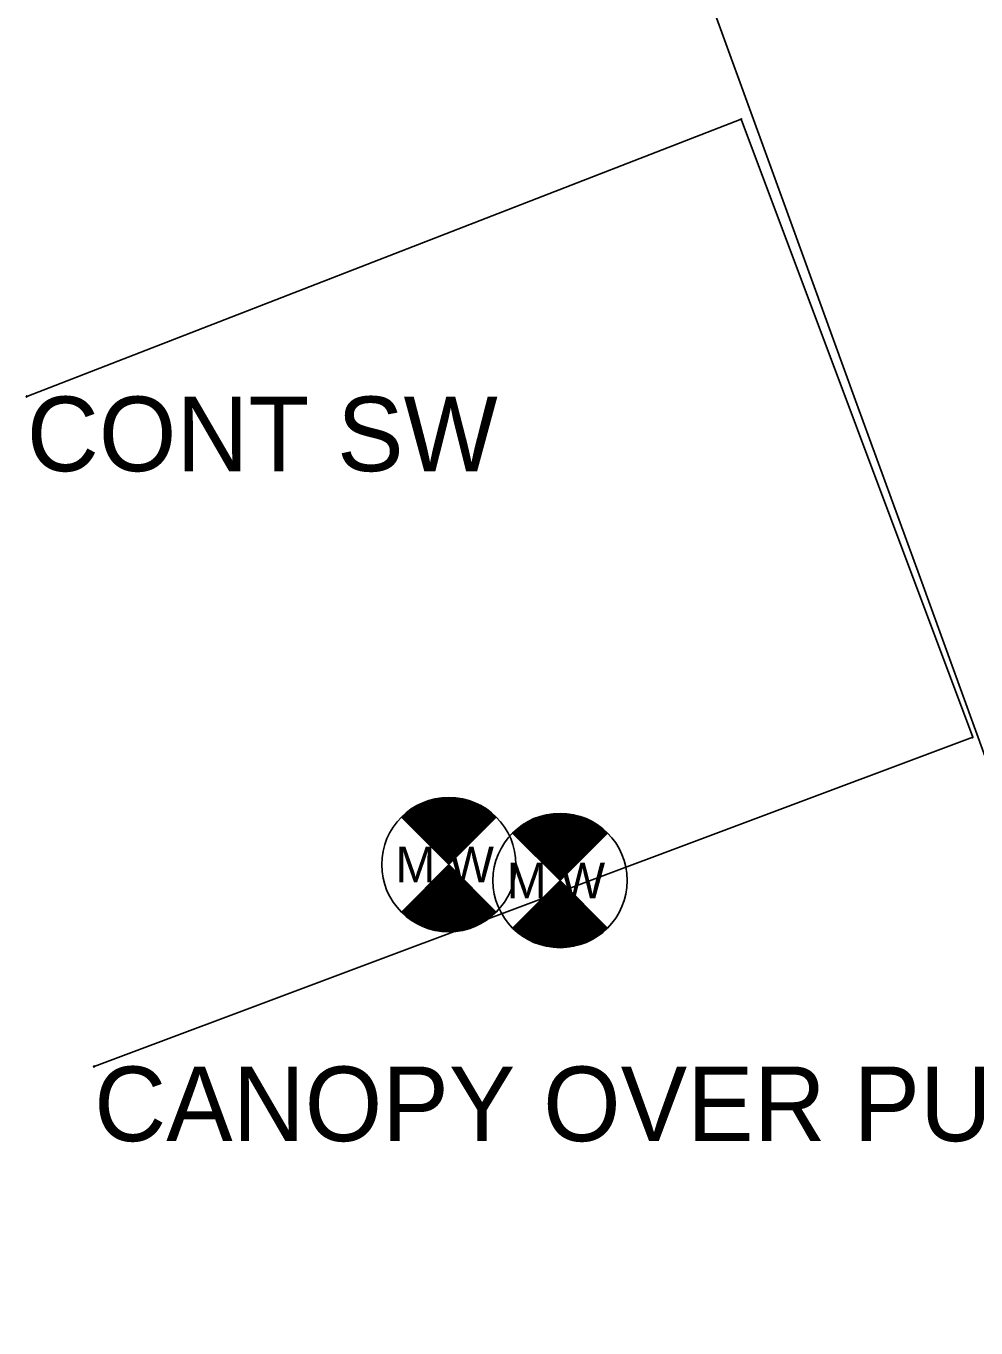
# Model space of a CAD drawing. Extents: x 997398 to 1003416, y 334596 to 337085.
# Drawn here: x 999486 to 999549.7, y 336485.6 to 336572.9 of the extents above; entities that cross this region are included whole.
import ezdxf

# ---------------------------------------------------------------- set-up
doc = ezdxf.new("R2010")
doc.units = 0
for name, color, linetype in [('S_BUILDING', 7, 'Continuous'), ('S_BUILDING_ANNOT', 7, 'Continuous'), ('S_CURB', 7, 'Continuous'), ('S_STR_PT_SYM', 7, 'Continuous'), ('S_TANK', 7, 'Continuous')]:
    doc.layers.add(name, color=color, linetype=linetype)

msp = doc.modelspace()

# ---------------------------------------------------------------- linework, layer by layer
at = {"layer": 'S_BUILDING'}
for p, q in [((999533.938, 336566.625), (999486.042, 336548.04)), ((999549.456, 336525.216), (999533.938, 336566.625)), ((999490.557, 336503.139), (999549.456, 336525.216))]:
    msp.add_line(p, q, dxfattribs=at)
at = {"layer": 'S_CURB'}
msp.add_lwpolyline([(999499.195, 336612.107), (999510.843, 336606.264), (999522.491, 336600.42), (999529.871, 336580.074), (999537.252, 336559.729), (999541.599, 336547.787), (999545.946, 336535.846), (999550.293, 336523.904), (999554.639, 336511.963), (999561.972, 336489.389), (999569.304, 336466.815), (999574.031, 336451.55), (999576.612, 336447.065), (999581.429, 336446.088), (999583.605, 336447.704)], dxfattribs=at)
at = {"layer": 'S_STR_PT_SYM'}
for points in [[(999533.938, 336566.625), (999533.938, 336566.675), (999533.938, 336566.625), (999533.888, 336566.625), (999533.938, 336566.625), (999533.938, 336566.575), (999533.938, 336566.625), (999533.988, 336566.625)], [(999486.042, 336548.04), (999486.042, 336548.09), (999486.042, 336548.04), (999485.992, 336548.04), (999486.042, 336548.04), (999486.042, 336547.99), (999486.042, 336548.04), (999486.092, 336548.04)], [(999549.456, 336525.216), (999549.456, 336525.266), (999549.456, 336525.216), (999549.406, 336525.216), (999549.456, 336525.216), (999549.456, 336525.166), (999549.456, 336525.216), (999549.506, 336525.216)], [(999490.557, 336503.139), (999490.557, 336503.189), (999490.557, 336503.139), (999490.506, 336503.139), (999490.557, 336503.139), (999490.557, 336503.089), (999490.557, 336503.139), (999490.606, 336503.139)]]:
    msp.add_lwpolyline(points, dxfattribs=at)
at = {"layer": 'S_TANK'}
for p, q in [((999511.268, 336519.741), (999512.12, 336520.594)), ((999511.31, 336519.699), (999512.302, 336520.691)), ((999511.353, 336519.657), (999512.466, 336520.77)), ((999511.395, 336519.614), (999512.617, 336520.836)), ((999511.437, 336519.572), (999512.757, 336520.891)), ((999511.48, 336519.529), (999512.888, 336520.938)), ((999511.522, 336519.487), (999513.013, 336520.978)), ((999511.565, 336519.444), (999513.133, 336521.013)), ((999511.607, 336519.402), (999513.248, 336521.043)), ((999511.65, 336519.36), (999513.359, 336521.069)), ((999511.692, 336519.317), (999513.467, 336521.092)), ((999511.734, 336519.275), (999513.57, 336521.11)), ((999511.777, 336519.232), (999513.671, 336521.127)), ((999511.819, 336519.19), (999513.77, 336521.14)), ((999511.862, 336519.147), (999513.866, 336521.151)), ((999511.904, 336519.105), (999513.959, 336521.16)), ((999511.946, 336519.063), (999514.051, 336521.167)), ((999511.989, 336519.02), (999514.14, 336521.171)), ((999512.031, 336518.978), (999514.228, 336521.174)), ((999512.074, 336518.935), (999514.314, 336521.176)), ((999512.116, 336518.893), (999514.398, 336521.175)), ((999512.159, 336518.85), (999514.482, 336521.174)), ((999512.201, 336518.808), (999514.563, 336521.17)), ((999512.243, 336518.766), (999514.643, 336521.165)), ((999512.286, 336518.723), (999514.721, 336521.159)), ((999512.328, 336518.681), (999514.799, 336521.152)), ((999512.371, 336518.638), (999514.875, 336521.143)), ((999512.413, 336518.596), (999514.95, 336521.133)), ((999512.456, 336518.553), (999515.024, 336521.122)), ((999512.498, 336518.511), (999515.097, 336521.11)), ((999512.54, 336518.469), (999515.169, 336521.097)), ((999512.583, 336518.426), (999515.24, 336521.083)), ((999512.625, 336518.384), (999515.31, 336521.068)), ((999512.668, 336518.341), (999515.379, 336521.053)), ((999512.71, 336518.299), (999515.447, 336521.036)), ((999512.753, 336518.257), (999515.514, 336521.018)), ((999512.795, 336518.214), (999515.58, 336520.999)), ((999512.837, 336518.172), (999515.646, 336520.98)), ((999512.88, 336518.129), (999515.71, 336520.96)), ((999512.922, 336518.087), (999515.774, 336520.939)), ((999512.965, 336518.044), (999515.837, 336520.917)), ((999513.007, 336518.002), (999515.9, 336520.894)), ((999513.05, 336517.96), (999515.961, 336520.871)), ((999513.092, 336517.917), (999516.022, 336520.847)), ((999513.134, 336517.875), (999516.082, 336520.822)), ((999513.177, 336517.832), (999516.141, 336520.796)), ((999513.219, 336517.79), (999516.2, 336520.77)), ((999513.262, 336517.747), (999516.257, 336520.743)), ((999513.304, 336517.705), (999516.315, 336520.716)), ((999513.347, 336517.663), (999516.371, 336520.687)), ((999513.389, 336517.62), (999516.427, 336520.659)), ((999513.431, 336517.578), (999516.483, 336520.629)), ((999513.474, 336517.535), (999516.537, 336520.599)), ((999513.516, 336517.493), (999516.592, 336520.568)), ((999513.559, 336517.45), (999516.645, 336520.536)), ((999511.183, 336519.826), (999511.63, 336520.273)), ((999511.225, 336519.784), (999511.907, 336520.465)), ((999513.601, 336517.408), (999516.698, 336520.504)), ((999513.644, 336517.366), (999516.75, 336520.472)), ((999513.686, 336517.323), (999516.801, 336520.438)), ((999513.728, 336517.281), (999516.852, 336520.404)), ((999513.771, 336517.238), (999516.902, 336520.37)), ((999513.813, 336517.196), (999516.952, 336520.335)), ((999513.856, 336517.153), (999517.001, 336520.299)), ((999513.898, 336517.111), (999517.05, 336520.263)), ((999513.941, 336517.069), (999517.098, 336520.226)), ((999513.983, 336517.026), (999517.145, 336520.188)), ((999514.025, 336516.984), (999517.192, 336520.151)), ((999514.068, 336516.941), (999517.238, 336520.112)), ((999514.11, 336516.899), (999517.284, 336520.073)), ((999514.153, 336516.856), (999517.329, 336520.033)), ((999514.195, 336516.814), (999517.374, 336519.993)), ((999514.238, 336516.772), (999517.418, 336519.952)), ((999514.28, 336516.729), (999517.461, 336519.91)), ((999514.322, 336516.687), (999517.504, 336519.869)), ((999518.808, 336518.586), (999519.922, 336519.7)), ((999518.85, 336518.544), (999520.072, 336519.766)), ((999518.893, 336518.502), (999520.212, 336519.821)), ((999518.935, 336518.459), (999520.344, 336519.868)), ((999518.978, 336518.417), (999520.469, 336519.908)), ((999519.02, 336518.374), (999520.588, 336519.942)), ((999519.062, 336518.332), (999520.703, 336519.973)), ((999519.105, 336518.289), (999520.814, 336519.999)), ((999519.147, 336518.247), (999520.922, 336520.022)), ((999519.19, 336518.205), (999521.026, 336520.04)), ((999519.232, 336518.162), (999521.126, 336520.056)), ((999519.275, 336518.12), (999521.225, 336520.07)), ((999519.317, 336518.077), (999521.321, 336520.081)), ((999519.359, 336518.035), (999521.414, 336520.09)), ((999519.402, 336517.993), (999521.506, 336520.097)), ((999519.444, 336517.95), (999521.596, 336520.101)), ((999519.487, 336517.908), (999521.683, 336520.104)), ((999519.529, 336517.865), (999521.77, 336520.106)), ((999519.572, 336517.823), (999521.854, 336520.105)), ((999519.614, 336517.78), (999521.937, 336520.103)), ((999519.656, 336517.738), (999522.018, 336520.1)), ((999519.699, 336517.696), (999522.099, 336520.095)), ((999519.741, 336517.653), (999522.177, 336520.089)), ((999519.784, 336517.611), (999522.255, 336520.082)), ((999519.826, 336517.568), (999522.331, 336520.073)), ((999519.869, 336517.526), (999522.406, 336520.063)), ((999519.911, 336517.483), (999522.48, 336520.052)), ((999519.953, 336517.441), (999522.553, 336520.04)), ((999519.996, 336517.399), (999522.624, 336520.027)), ((999520.038, 336517.356), (999522.695, 336520.013)), ((999520.081, 336517.314), (999522.765, 336519.998)), ((999520.123, 336517.271), (999522.834, 336519.982)), ((999520.166, 336517.229), (999522.902, 336519.965)), ((999520.208, 336517.186), (999522.97, 336519.948)), ((999520.25, 336517.144), (999523.036, 336519.929)), ((999520.293, 336517.102), (999523.101, 336519.91)), ((999520.335, 336517.059), (999523.166, 336519.889)), ((999520.378, 336517.017), (999523.23, 336519.869)), ((999520.42, 336516.974), (999523.292, 336519.847)), ((999520.463, 336516.932), (999523.355, 336519.824)), ((999520.505, 336516.889), (999523.416, 336519.801)), ((999520.547, 336516.847), (999523.477, 336519.777)), ((999520.59, 336516.805), (999523.537, 336519.752)), ((999520.632, 336516.762), (999523.596, 336519.726)), ((999520.675, 336516.72), (999523.655, 336519.7)), ((999520.717, 336516.677), (999523.713, 336519.673)), ((999518.638, 336518.756), (999519.085, 336519.203)), ((999518.681, 336518.714), (999519.362, 336519.395)), ((999518.723, 336518.671), (999519.576, 336519.524)), ((999518.765, 336518.629), (999519.758, 336519.621)), ((999520.76, 336516.635), (999523.77, 336519.646)), ((999520.802, 336516.592), (999523.827, 336519.617)), ((999520.844, 336516.55), (999523.883, 336519.588)), ((999520.887, 336516.508), (999523.938, 336519.559)), ((999520.929, 336516.465), (999523.993, 336519.529)), ((999520.972, 336516.423), (999524.047, 336519.498)), ((999521.014, 336516.38), (999524.1, 336519.466)), ((999521.057, 336516.338), (999524.153, 336519.434)), ((999521.099, 336516.295), (999524.205, 336519.401)), ((999521.141, 336516.253), (999524.257, 336519.368)), ((999521.184, 336516.211), (999524.308, 336519.334)), ((999521.226, 336516.168), (999524.358, 336519.3)), ((999521.269, 336516.126), (999524.408, 336519.265)), ((999521.311, 336516.083), (999524.457, 336519.229)), ((999521.354, 336516.041), (999524.505, 336519.193)), ((999521.396, 336515.998), (999524.553, 336519.156)), ((999521.438, 336515.956), (999524.601, 336519.118)), ((999521.481, 336515.914), (999524.648, 336519.081)), ((999521.523, 336515.871), (999524.694, 336519.042)), ((999521.566, 336515.829), (999524.74, 336519.003)), ((999521.608, 336515.786), (999524.785, 336518.963)), ((999521.65, 336515.744), (999524.829, 336518.923)), ((999521.693, 336515.701), (999524.873, 336518.882)), ((999521.735, 336515.659), (999524.916, 336518.84)), ((999521.778, 336515.617), (999524.96, 336518.798)), ((999511.183, 336513.463), (999514.365, 336516.645)), ((999511.226, 336513.421), (999514.407, 336516.602)), ((999511.27, 336513.38), (999514.449, 336516.56)), ((999511.314, 336513.34), (999514.492, 336516.517)), ((999511.359, 336513.299), (999514.534, 336516.475)), ((999511.404, 336513.26), (999514.577, 336516.432)), ((999511.45, 336513.221), (999514.619, 336516.39)), ((999511.497, 336513.183), (999514.662, 336516.348)), ((999511.544, 336513.145), (999514.704, 336516.305)), ((999511.591, 336513.108), (999514.746, 336516.263)), ((999511.64, 336513.072), (999514.789, 336516.22)), ((999511.689, 336513.035), (999514.831, 336516.178)), ((999511.738, 336513), (999514.874, 336516.135)), ((999511.788, 336512.965), (999514.916, 336516.093)), ((999511.839, 336512.931), (999514.959, 336516.051)), ((999511.89, 336512.897), (999515.001, 336516.008)), ((999511.942, 336512.864), (999515.043, 336515.966)), ((999511.995, 336512.832), (999515.086, 336515.923)), ((999512.048, 336512.8), (999515.128, 336515.881)), ((999512.101, 336512.769), (999515.171, 336515.838)), ((999512.156, 336512.739), (999515.213, 336515.796)), ((999512.21, 336512.708), (999515.256, 336515.754)), ((999512.266, 336512.679), (999515.298, 336515.711)), ((999512.322, 336512.651), (999515.34, 336515.669)), ((999512.379, 336512.623), (999515.383, 336515.626)), ((999512.437, 336512.596), (999515.425, 336515.584)), ((999512.495, 336512.569), (999515.468, 336515.541)), ((999512.554, 336512.543), (999515.51, 336515.499)), ((999512.614, 336512.518), (999515.552, 336515.457)), ((999512.674, 336512.494), (999515.595, 336515.414)), ((999512.735, 336512.47), (999515.637, 336515.372)), ((999512.797, 336512.447), (999515.68, 336515.329)), ((999518.638, 336512.393), (999521.82, 336515.574)), ((999518.682, 336512.351), (999521.862, 336515.532)), ((999518.725, 336512.31), (999521.905, 336515.49)), ((999518.77, 336512.27), (999521.947, 336515.447)), ((999518.814, 336512.229), (999521.99, 336515.405)), ((999518.86, 336512.19), (999522.032, 336515.362)), ((999518.906, 336512.151), (999522.075, 336515.32)), ((999512.86, 336512.424), (999515.722, 336515.287)), ((999512.923, 336512.403), (999515.765, 336515.244)), ((999512.987, 336512.382), (999515.807, 336515.202)), ((999513.052, 336512.363), (999515.849, 336515.16)), ((999513.118, 336512.344), (999515.892, 336515.117)), ((999513.185, 336512.325), (999515.934, 336515.075)), ((999513.253, 336512.308), (999515.977, 336515.032)), ((999513.321, 336512.292), (999516.019, 336514.99)), ((999513.391, 336512.276), (999516.062, 336514.947)), ((999513.461, 336512.262), (999516.104, 336514.905)), ((999513.532, 336512.248), (999516.146, 336514.863)), ((999513.604, 336512.236), (999516.189, 336514.82)), ((999513.678, 336512.225), (999516.231, 336514.778)), ((999513.752, 336512.214), (999516.274, 336514.735)), ((999513.828, 336512.205), (999516.316, 336514.693)), ((999513.905, 336512.197), (999516.359, 336514.651)), ((999513.983, 336512.19), (999516.401, 336514.608)), ((999514.062, 336512.185), (999516.443, 336514.566)), ((999514.143, 336512.181), (999516.486, 336514.523)), ((999514.225, 336512.178), (999516.528, 336514.481)), ((999514.309, 336512.176), (999516.571, 336514.438)), ((999518.952, 336512.113), (999522.117, 336515.277)), ((999519, 336512.075), (999522.159, 336515.235)), ((999519.047, 336512.038), (999522.202, 336515.193)), ((999519.095, 336512.001), (999522.244, 336515.15)), ((999519.144, 336511.965), (999522.287, 336515.108)), ((999519.194, 336511.93), (999522.329, 336515.065)), ((999519.244, 336511.895), (999522.371, 336515.023)), ((999519.294, 336511.861), (999522.414, 336514.98)), ((999519.346, 336511.827), (999522.456, 336514.938)), ((999519.397, 336511.794), (999522.499, 336514.896)), ((999519.45, 336511.762), (999522.541, 336514.853)), ((999519.503, 336511.73), (999522.584, 336514.811)), ((999519.557, 336511.699), (999522.626, 336514.768)), ((999519.611, 336511.668), (999522.668, 336514.726)), ((999519.666, 336511.638), (999522.711, 336514.683)), ((999519.722, 336511.609), (999522.753, 336514.641)), ((999519.778, 336511.581), (999522.796, 336514.599)), ((999519.835, 336511.553), (999522.838, 336514.556)), ((999519.892, 336511.525), (999522.881, 336514.514)), ((999519.95, 336511.499), (999522.923, 336514.471)), ((999520.01, 336511.473), (999522.965, 336514.429)), ((999514.394, 336512.177), (999516.613, 336514.396)), ((999514.481, 336512.179), (999516.656, 336514.354)), ((999514.57, 336512.183), (999516.698, 336514.311)), ((999514.66, 336512.188), (999516.74, 336514.269)), ((999514.753, 336512.196), (999516.783, 336514.226)), ((999514.848, 336512.206), (999516.825, 336514.184)), ((999514.945, 336512.218), (999516.868, 336514.141)), ((999515.044, 336512.233), (999516.91, 336514.099)), ((999515.147, 336512.251), (999516.953, 336514.057)), ((999515.252, 336512.272), (999516.995, 336514.014)), ((999515.361, 336512.295), (999517.037, 336513.972)), ((999515.474, 336512.323), (999517.08, 336513.929)), ((999515.592, 336512.356), (999517.122, 336513.887)), ((999515.714, 336512.394), (999517.165, 336513.844)), ((999515.843, 336512.438), (999517.207, 336513.802)), ((999515.978, 336512.488), (999517.25, 336513.76)), ((999516.123, 336512.548), (999517.292, 336513.717)), ((999516.279, 336512.619), (999517.334, 336513.675)), ((999516.45, 336512.705), (999517.377, 336513.632)), ((999516.646, 336512.817), (999517.419, 336513.59)), ((999520.069, 336511.448), (999523.008, 336514.387)), ((999520.13, 336511.423), (999523.05, 336514.344)), ((999520.191, 336511.399), (999523.093, 336514.302)), ((999520.253, 336511.377), (999523.135, 336514.259)), ((999520.315, 336511.354), (999523.178, 336514.217)), ((999520.379, 336511.333), (999523.22, 336514.174)), ((999520.443, 336511.312), (999523.262, 336514.132)), ((999520.508, 336511.292), (999523.305, 336514.09)), ((999520.574, 336511.274), (999523.347, 336514.047)), ((999520.64, 336511.255), (999523.39, 336514.005)), ((999520.708, 336511.238), (999523.432, 336513.962)), ((999520.776, 336511.222), (999523.475, 336513.92)), ((999520.846, 336511.206), (999523.517, 336513.877)), ((999520.916, 336511.192), (999523.559, 336513.835)), ((999520.988, 336511.178), (999523.602, 336513.793)), ((999521.06, 336511.166), (999523.644, 336513.75)), ((999521.134, 336511.154), (999523.687, 336513.708)), ((999521.208, 336511.144), (999523.729, 336513.665)), ((999521.284, 336511.135), (999523.772, 336513.623)), ((999521.36, 336511.127), (999523.814, 336513.58)), ((999516.884, 336512.97), (999517.462, 336513.547)), ((999517.246, 336513.247), (999517.504, 336513.505)), ((999521.439, 336511.12), (999523.856, 336513.538)), ((999521.518, 336511.115), (999523.899, 336513.496)), ((999521.599, 336511.11), (999523.941, 336513.453)), ((999521.681, 336511.108), (999523.984, 336513.411)), ((999521.764, 336511.106), (999524.026, 336513.368)), ((999521.85, 336511.107), (999524.069, 336513.326)), ((999521.936, 336511.109), (999524.111, 336513.283)), ((999522.025, 336511.113), (999524.153, 336513.241)), ((999522.116, 336511.118), (999524.196, 336513.199)), ((999522.208, 336511.126), (999524.238, 336513.156)), ((999522.303, 336511.136), (999524.281, 336513.114)), ((999522.4, 336511.148), (999524.323, 336513.071)), ((999522.499, 336511.163), (999524.366, 336513.029)), ((999522.602, 336511.181), (999524.408, 336512.986)), ((999522.708, 336511.201), (999524.45, 336512.944)), ((999522.816, 336511.225), (999524.493, 336512.902)), ((999522.929, 336511.253), (999524.535, 336512.859)), ((999523.047, 336511.286), (999524.578, 336512.817)), ((999523.17, 336511.324), (999524.62, 336512.774)), ((999523.298, 336511.367), (999524.663, 336512.732)), ((999523.434, 336511.418), (999524.705, 336512.689)), ((999523.578, 336511.478), (999524.747, 336512.647)), ((999523.734, 336511.549), (999524.79, 336512.605)), ((999523.905, 336511.635), (999524.832, 336512.562)), ((999524.102, 336511.747), (999524.875, 336512.52)), ((999524.339, 336511.9), (999524.917, 336512.477)), ((999524.702, 336512.177), (999524.96, 336512.435))]:
    msp.add_line(p, q, dxfattribs=at)
for points in [[(999511.151, 336519.858), (999514.333, 336516.676), (999511.151, 336513.494)], [(999517.515, 336519.858), (999514.333, 336516.676), (999517.515, 336513.494)], [(999518.606, 336518.788), (999521.788, 336515.606), (999518.606, 336512.424)], [(999524.97, 336518.788), (999521.788, 336515.606), (999524.97, 336512.424)]]:
    msp.add_lwpolyline(points, dxfattribs=at)
for centre in [(999514.333, 336516.676), (999521.788, 336515.606)]:
    msp.add_circle(centre, 4.5, dxfattribs=at)

# ---------------------------------------------------------------- texts
at = {"layer": 'S_BUILDING_ANNOT'}
for s, p in [('CONT SW', (999486.042, 336543.04)), ('CANOPY OVER PUMP ISLANDS', (999490.557, 336498.139))]:
    msp.add_text(s, height=5, dxfattribs=at).set_placement(p)
at = {"layer": 'S_TANK'}
for p in [(999510.761, 336515.476), (999518.217, 336514.406)]:
    msp.add_text('M W', height=2.4, rotation=360, dxfattribs=at).set_placement(p)

doc.saveas('drawing.dxf')
